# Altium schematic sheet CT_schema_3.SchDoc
size 283 x 174 mm
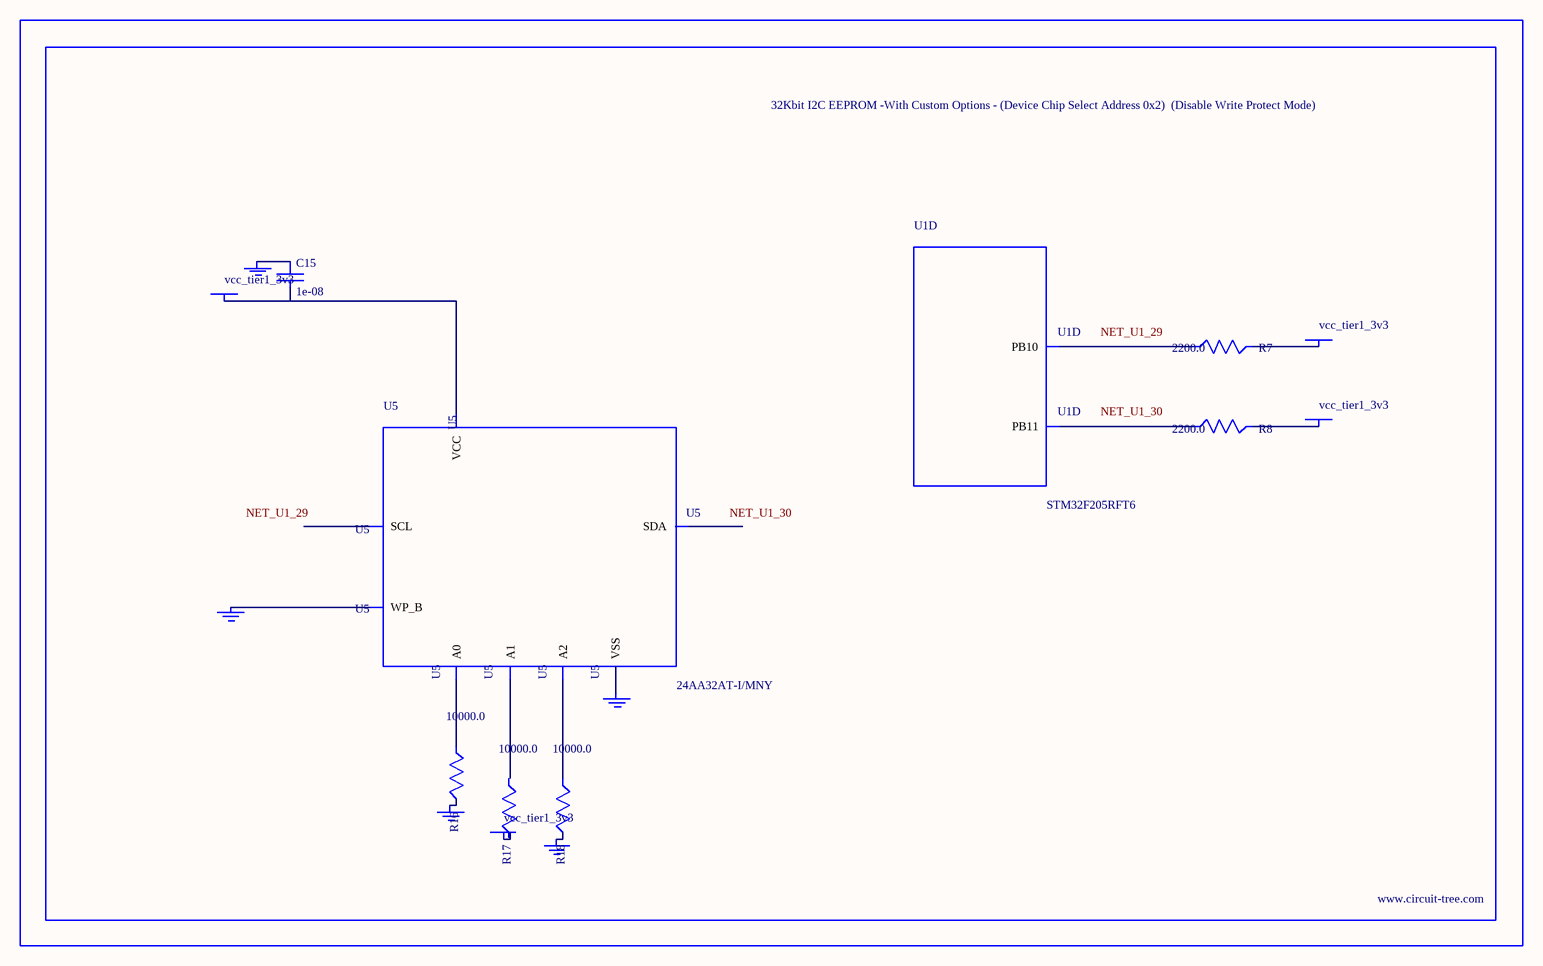
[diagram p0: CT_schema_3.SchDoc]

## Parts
BORDER2  (no value)
C15  1e-08  [C0402]
GND_INSTANCE_2_0  (no value)
GND_INSTANCE_2_1  (no value)
GND_INSTANCE_2_2  (no value)
GND_INSTANCE_2_3  (no value)
GND_INSTANCE_2_4  (no value)
POWER_INSTANCE_2_0  vcc_tier1_3v3
POWER_INSTANCE_2_1  vcc_tier1_3v3
POWER_INSTANCE_2_2  vcc_tier1_3v3
POWER_INSTANCE_2_3  vcc_tier1_3v3
R7  2200.0  [R0603]
R8  2200.0  [R0603]
R16  10000.0  [R0603]
R17  10000.0  [R0603]
R18  10000.0  [R0603]
U1  STM32F205RFT6  [LQFP64]  (part D of 7)
U5  24AA32AT-I/MNY  [TDFN-8/6MM]

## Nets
NetC15_1: C15.1 GND_INSTANCE_2_3.0(GND)
NetC15_2: C15.2 POWER_INSTANCE_2_1.0(PWR) U5.8(VCC)
NetGND_INSTANCE_2_0_0: GND_INSTANCE_2_0.0(GND) R16.2
NetGND_INSTANCE_2_1_0: GND_INSTANCE_2_1.0(GND) R18.2
NetGND_INSTANCE_2_2_0: GND_INSTANCE_2_2.0(GND) U5.7(WP_B)
NetGND_INSTANCE_2_4_0: GND_INSTANCE_2_4.0(GND) U5.4(VSS)
NetPOWER_INSTANCE_2_2_0: POWER_INSTANCE_2_2.0(PWR) R7.2
NetPOWER_INSTANCE_2_3_0: POWER_INSTANCE_2_3.0(PWR) R8.2
NetR7_1: R7.1 U1.29(PB10)
NetR8_1: R8.1 U1.30(PB11)
NetR16_1: R16.1 U5.1(A0)
NetR18_1: R18.1 U5.3(A2)

Not connected (* = marked no-connect by the designer): POWER_INSTANCE_2_0 0(PWR); R17 1 2; U5 2(A1) 5(SDA) 6(SCL)

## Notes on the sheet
- Labels drawn without touching a wire or pin: NET_U1_29, NET_U1_30

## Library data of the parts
BORDER2 = BORDER_PAGE2
C15 = C0402C103K3RAC
GND_INSTANCE_2_0-GND_INSTANCE_2_4 = GND
POWER_INSTANCE_2_0-POWER_INSTANCE_2_3 = PWR
R7 R8 = RC0603JR-072K2L
R16-R18 = RC0603JR-0710KL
